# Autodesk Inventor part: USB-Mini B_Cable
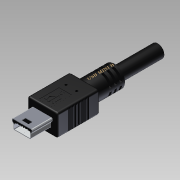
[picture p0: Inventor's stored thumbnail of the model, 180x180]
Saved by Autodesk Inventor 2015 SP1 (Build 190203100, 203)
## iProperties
Created: 2015-05
Part Number: USB-Mini B_Cable
Material: Generic
Document SubType Name: Modeling
Designer: kazys
Density: 1 g/cm^3
Appearance: Default
Author: kazys
Author: Ildong
Description: SolidWorks IGES file using analytic representation for surfaces
Creation Date: 2013-11-27
Sending System: SolidWorks 2012
Preprocessor: SolidWorks 2012
Minimum Resolution: 0.0
Sending System Product ID: USB-Mini B_Cable(1)
Receiving System Product ID: USB-Mini B_Cable(1)
Sent Units: Millimeter
Translation Standard: IGES 5.3
Model Creation Time: 2013-11-27
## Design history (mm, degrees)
node "USB-Mini B_Cable1"
feature "Composite1"
body "Srf1"
